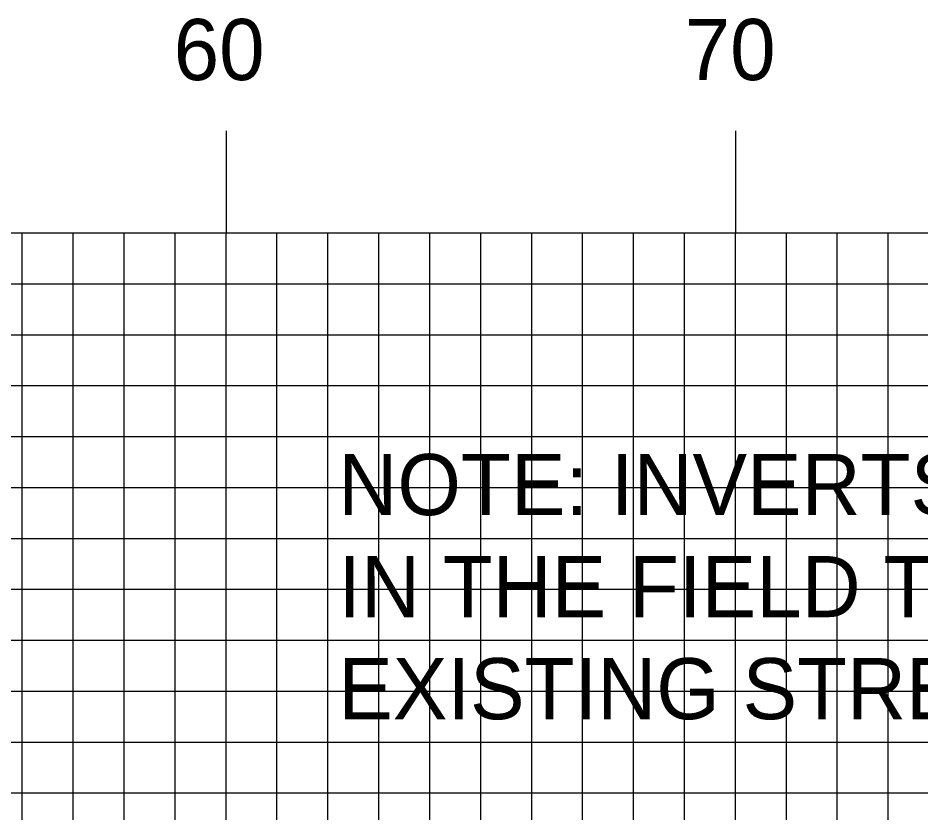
# Model space of a CAD drawing. Extents: x 1814915 to 1815259, y 442591 to 442811.
# Drawn here: x 1815136.94 to 1815154.66, y 442757.27 to 442772.88 of the extents above; entities that cross this region are included whole.
import ezdxf

# ---------------------------------------------------------------- set-up
doc = ezdxf.new("R2010")
doc.units = 0
for name, color, linetype in [('ANNOTATION', 7, 'Continuous'), ('H_V ANNOTATION', 7, 'Continuous'), ('MAJOR', 7, 'Continuous'), ('MINOR', 7, 'Continuous')]:
    doc.layers.add(name, color=color, linetype=linetype)

msp = doc.modelspace()

# ---------------------------------------------------------------- linework, layer by layer
at = {"layer": 'MAJOR'}
for p, q in [((1815141.021, 442770.669), (1815141.021, 442768.665)), ((1815151.021, 442770.669), (1815151.021, 442768.665)), ((1814941.021, 442768.665), (1815221.021, 442768.665)), ((1814941.021, 442768.665), (1815221.021, 442768.665)), ((1815141.021, 442743.665), (1815141.021, 442768.665)), ((1815151.021, 442743.665), (1815151.021, 442768.665)), ((1814941.021, 442763.665), (1815221.021, 442763.665)), ((1814941.021, 442758.665), (1815221.021, 442758.665))]:
    msp.add_line(p, q, dxfattribs=at)
at = {"layer": 'MINOR'}
for p, q in [((1815137.021, 442743.665), (1815137.021, 442768.665)), ((1815138.021, 442743.665), (1815138.021, 442768.665)), ((1815139.021, 442743.665), (1815139.021, 442768.665)), ((1815140.021, 442743.665), (1815140.021, 442768.665)), ((1815142.021, 442743.665), (1815142.021, 442768.665)), ((1815143.021, 442743.665), (1815143.021, 442768.665)), ((1815144.021, 442743.665), (1815144.021, 442768.665)), ((1815145.021, 442743.665), (1815145.021, 442768.665)), ((1815146.021, 442743.665), (1815146.021, 442768.665)), ((1815147.021, 442743.665), (1815147.021, 442768.665)), ((1815148.021, 442743.665), (1815148.021, 442768.665)), ((1815149.021, 442743.665), (1815149.021, 442768.665)), ((1815150.021, 442743.665), (1815150.021, 442768.665)), ((1815152.021, 442743.665), (1815152.021, 442768.665)), ((1815153.021, 442743.665), (1815153.021, 442768.665)), ((1815154.021, 442743.665), (1815154.021, 442768.665)), ((1814941.021, 442767.665), (1815221.021, 442767.665)), ((1814941.021, 442766.665), (1815221.021, 442766.665)), ((1814941.021, 442765.665), (1815221.021, 442765.665)), ((1814941.021, 442764.665), (1815221.021, 442764.665)), ((1814941.021, 442762.665), (1815221.021, 442762.665)), ((1814941.021, 442761.665), (1815221.021, 442761.665)), ((1814941.021, 442760.665), (1815221.021, 442760.665)), ((1814941.021, 442759.665), (1815221.021, 442759.665)), ((1814941.021, 442757.665), (1815221.021, 442757.665))]:
    msp.add_line(p, q, dxfattribs=at)

# ---------------------------------------------------------------- texts
at = {"layer": 'ANNOTATION'}
for s, p in [('NOTE: INVERTS SHALL BE ADJUSTED ', (1815143.225, 442763.121)), ('IN THE FIELD TO 6" BELOW', (1815143.225, 442761.117)), ('EXISTING STREAMBED ELEVATIONS', (1815143.225, 442759.113))]:
    msp.add_text(s, height=1.2, dxfattribs=at).set_placement(p)
at = {"layer": 'H_V ANNOTATION'}
for s, p in [('60', (1815139.993, 442771.665)), ('70', (1815150.025, 442771.665))]:
    msp.add_text(s, height=1.2, dxfattribs=at).set_placement(p)

doc.saveas('drawing.dxf')
